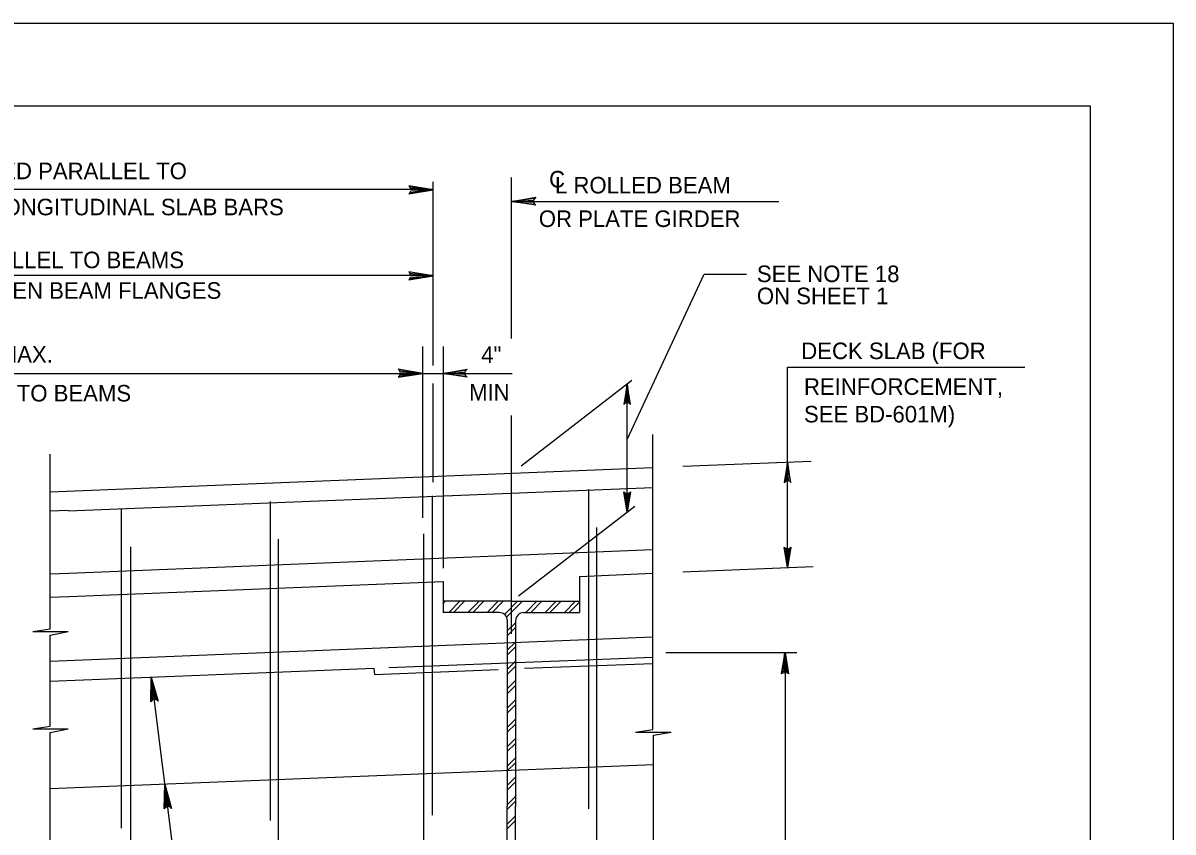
# Model space of a CAD drawing. Extents: x 640009 to 641706, y 298547 to 299735.
# Drawn here: x 641482.9 to 641691.5, y 299588.5 to 299735.2 of the extents above; entities that cross this region are included whole.
import ezdxf

# ---------------------------------------------------------------- set-up
doc = ezdxf.new("R2010")
doc.units = 0
doc.layers.add('1', color=7, linetype='Continuous')
doc.layers.add('PLT-BNDY', color=7, linetype='Continuous')

msp = doc.modelspace()

# ---------------------------------------------------------------- linework, layer by layer
at = {"layer": '1'}
for p, q in [((640890.47, 299720.17), (641676.47, 299720.17)), ((640890.47, 299720.17), (641676.47, 299720.17)), ((641676.47, 299720.17), (641676.47, 299156.17)), ((641676.47, 299720.17), (641676.47, 299156.17)), ((641557.24, 299706.36), (641557.24, 299673.12)), ((641571.49, 299677.96), (641571.49, 299707.14)), ((641411.49, 299705.06), (641557.24, 299705.06)), ((641571.49, 299702.85), (641620.02, 299702.85)), ((641592.47, 299659.66), (641606.46, 299689.66)), ((641606.46, 299689.66), (641614.1, 299689.66)), ((641411.49, 299689.46), (641557.24, 299689.46)), ((641555.37, 299676.52), (641555.37, 299645.47)), ((641559.12, 299676.52), (641559.12, 299636.37)), ((641393.08, 299671.65), (641571.62, 299671.65)), ((641621.59, 299636.45), (641621.59, 299672.77)), ((641621.59, 299672.77), (641664.58, 299672.77)), ((641557.24, 299669.85), (641557.24, 299651.97)), ((641573.24, 299654.91), (641593.36, 299670.41)), ((641592.47, 299646.5), (641592.47, 299669.72)), ((641571.49, 299624.46), (641571.49, 299664.06)), ((641597.12, 299607.1), (641597.12, 299660.6)), ((641487.87, 299625.37), (641487.87, 299657)), ((641487.87, 299650.22), (641597.12, 299654.6)), ((641602.6, 299654.82), (641625.84, 299655.75)), ((641491.12, 299646.72), (641597.12, 299650.97)), ((641585.49, 299650.6), (641585.49, 299592.72)), ((641527.74, 299648.47), (641527.74, 299590.6)), ((641557.12, 299649.47), (641557.12, 299591.6)), ((641487.87, 299646.72), (641491.12, 299646.85)), ((641500.74, 299647.1), (641500.74, 299589.22)), ((641572.79, 299631.35), (641593.87, 299647.58)), ((641586.99, 299518.22), (641586.99, 299643.72)), ((641555.62, 299517.71), (641555.62, 299642.6)), ((641491.24, 299635.47), (641597.12, 299639.72)), ((641502.49, 299515.64), (641502.49, 299640.22)), ((641529.24, 299516.87), (641529.24, 299641.6)), ((641487.87, 299635.34), (641491.24, 299635.47)), ((641583.87, 299634.86), (641597.12, 299635.47)), ((641602.6, 299635.69), (641626.2, 299636.64)), ((641491.24, 299631.22), (641559.12, 299633.94)), ((641559.12, 299633.94), (641559.12, 299628.35)), ((641583.87, 299634.86), (641583.87, 299628.35)), ((641487.87, 299631.09), (641491.24, 299631.22)), ((641571.49, 299630.35), (641559.12, 299630.35)), ((641571.49, 299630.35), (641559.12, 299630.35)), ((641559.12, 299630.35), (641559.12, 299629.35)), ((641571.49, 299630.35), (641559.12, 299630.35)), ((641559.12, 299630.35), (641559.12, 299628.35)), ((641571.49, 299630.35), (641583.87, 299630.35)), ((641571.49, 299630.35), (641583.87, 299630.35)), ((641571.49, 299630.35), (641583.87, 299630.35)), ((641583.87, 299630.35), (641583.87, 299629.35)), ((641583.87, 299630.35), (641583.87, 299628.35)), ((641569.24, 299628.35), (641559.12, 299628.35)), ((641569.24, 299628.35), (641559.12, 299628.35)), ((641573.74, 299628.35), (641583.87, 299628.35)), ((641573.74, 299628.35), (641583.87, 299628.35)), ((641484.74, 299624.87), (641487.87, 299625.37)), ((641570.74, 299626.85), (641570.74, 299593.22)), ((641570.74, 299626.85), (641570.74, 299593.22)), ((641572.24, 299626.85), (641572.24, 299593.22)), ((641572.24, 299626.85), (641572.24, 299593.22)), ((641484.74, 299624.87), (641491.12, 299624.87)), ((641487.87, 299624.22), (641491.12, 299624.87)), ((641487.87, 299615.9), (641487.87, 299624.22)), ((641487.87, 299619.52), (641597.12, 299623.9)), ((641487.99, 299624.87), (641487.99, 299624.87)), ((641599.49, 299621.1), (641623.24, 299621.1)), ((641621.12, 299621.1), (641621.12, 299518.87)), ((641549.24, 299618.35), (641597.12, 299620.22)), ((641573.87, 299618.22), (641597.12, 299619.1)), ((641487.87, 299615.9), (641546.62, 299618.22)), ((641506.19, 299616.62), (641519.99, 299506.6)), ((641546.74, 299617.1), (641546.62, 299618.22)), ((641546.74, 299617.1), (641569.12, 299617.97)), ((641487.87, 299607.73), (641487.87, 299615.9)), ((641484.74, 299607.23), (641487.87, 299607.73)), ((641484.74, 299607.23), (641491.12, 299607.23)), ((641487.87, 299606.58), (641491.12, 299607.23)), ((641487.87, 299581.6), (641487.87, 299606.58)), ((641487.99, 299607.23), (641487.99, 299607.23)), ((641593.99, 299606.6), (641597.12, 299607.1)), ((641593.99, 299606.6), (641600.49, 299606.6)), ((641597.24, 299606.1), (641600.49, 299606.6)), ((641597.24, 299606.6), (641597.24, 299606.6)), ((641597.24, 299530.08), (641597.24, 299606.1)), ((641487.87, 299596.39), (641597.24, 299600.74)), ((641570.74, 299516.21), (641570.74, 299593.22)), ((641570.74, 299516.21), (641570.74, 299593.22)), ((641572.24, 299516.21), (641572.24, 299593.22)), ((641572.24, 299516.21), (641572.24, 299593.22))]:
    msp.add_line(p, q, dxfattribs=at)
for points in [[(641553.08, 299704.42), (641553.25, 299704.73), (641557.32, 299704.95), (641553.08, 299704.42), (641552.87, 299704.23), (641557.32, 299704.95), (641553.25, 299705.15), (641553.09, 299705.46), (641557.32, 299704.95), (641552.87, 299705.68), (641553.09, 299705.46)], [(641575.73, 299702.32), (641575.56, 299702.63), (641571.49, 299702.85), (641575.73, 299702.32), (641575.94, 299702.13), (641571.49, 299702.85), (641575.56, 299703.05), (641575.72, 299703.36), (641571.49, 299702.85), (641575.94, 299703.58), (641575.72, 299703.36)], [(641553.08, 299688.81), (641553.25, 299689.13), (641557.32, 299689.35), (641553.08, 299688.81), (641552.87, 299688.63), (641557.32, 299689.35), (641553.25, 299689.55), (641553.09, 299689.85), (641557.32, 299689.35), (641552.87, 299690.08), (641553.09, 299689.85)], [(641551.2, 299671.14), (641551.38, 299671.45), (641555.44, 299671.67), (641551.2, 299671.14), (641550.99, 299670.95), (641555.44, 299671.67), (641551.38, 299671.87), (641551.22, 299672.18), (641555.44, 299671.67), (641550.99, 299672.4), (641551.22, 299672.18)], [(641563.28, 299671.14), (641563.1, 299671.45), (641559.04, 299671.67), (641563.28, 299671.14), (641563.49, 299670.95), (641559.04, 299671.67), (641563.1, 299671.87), (641563.26, 299672.18), (641559.04, 299671.67), (641563.49, 299672.4), (641563.26, 299672.18)], [(641592.91, 299666.18), (641592.65, 299666.33), (641592.47, 299669.72), (641592.91, 299666.18), (641593.07, 299666.01), (641592.47, 299669.72), (641592.3, 299666.33), (641592.05, 299666.2), (641592.47, 299669.72), (641591.86, 299666.01), (641592.05, 299666.2)], [(641622.03, 299652.04), (641621.77, 299652.19), (641621.59, 299655.58), (641622.03, 299652.04), (641622.19, 299651.87), (641621.59, 299655.58), (641621.42, 299652.19), (641621.17, 299652.06), (641621.59, 299655.58), (641620.98, 299651.87), (641621.17, 299652.06)], [(641592.91, 299650.03), (641592.65, 299649.89), (641592.47, 299646.5), (641592.91, 299650.03), (641593.07, 299650.21), (641592.47, 299646.5), (641592.3, 299649.89), (641592.05, 299650.02), (641592.47, 299646.5), (641591.86, 299650.21), (641592.05, 299650.02)], [(641622.03, 299639.99), (641621.77, 299639.84), (641621.59, 299636.45), (641622.03, 299639.99), (641622.19, 299640.17), (641621.59, 299636.45), (641621.42, 299639.84), (641621.17, 299639.98), (641621.59, 299636.45), (641620.98, 299640.17), (641621.17, 299639.98)], [(641559.12, 299629.97), (641559.49, 299630.35)], [(641560.12, 299628.35), (641562.12, 299630.35)], [(641560.99, 299628.35), (641562.99, 299630.35)], [(641563.62, 299628.35), (641565.62, 299630.35)], [(641564.49, 299628.35), (641566.49, 299630.35)], [(641567.12, 299628.35), (641569.12, 299630.35)], [(641567.99, 299628.35), (641569.99, 299630.35)], [(641570.24, 299627.97), (641572.62, 299630.35)], [(641570.62, 299627.47), (641573.49, 299630.35)], [(641574.12, 299628.35), (641576.12, 299630.35)], [(641574.99, 299628.35), (641576.99, 299630.35)], [(641577.62, 299628.35), (641579.62, 299630.35)], [(641578.49, 299628.35), (641580.49, 299630.35)], [(641581.12, 299628.35), (641583.12, 299630.35)], [(641581.99, 299628.35), (641583.87, 299630.22)], [(641583.74, 299628.35), (641583.87, 299628.47)], [(641570.74, 299624.97), (641572.24, 299626.47)], [(641570.74, 299624.1), (641572.24, 299625.6)], [(641570.74, 299621.47), (641572.24, 299622.97)], [(641570.74, 299620.6), (641572.24, 299622.1)], [(641620.62, 299617.35), (641620.99, 299617.47), (641621.12, 299621.1), (641620.62, 299617.35), (641620.49, 299617.22), (641621.12, 299621.1), (641621.37, 299617.47), (641621.62, 299617.35), (641621.12, 299621.1), (641621.74, 299617.22), (641621.62, 299617.35)], [(641621.55, 299617.52), (641621.29, 299617.67), (641621.1, 299621.06), (641621.55, 299617.52), (641621.71, 299617.35), (641621.1, 299621.06), (641620.94, 299617.67), (641620.68, 299617.54), (641621.1, 299621.06), (641620.5, 299617.35), (641620.68, 299617.54)], [(641570.74, 299617.97), (641572.24, 299619.47)], [(641506.29, 299612.3), (641506.49, 299612.47), (641506.19, 299616.62), (641506.29, 299612.3), (641506.09, 299612.12), (641506.19, 299616.62), (641506.88, 299612.63), (641507.24, 299612.42), (641506.19, 299616.62), (641507.41, 299612.22), (641507.24, 299612.42)], [(641570.74, 299617.1), (641572.24, 299618.6)], [(641570.74, 299614.47), (641572.24, 299615.97)], [(641570.74, 299613.6), (641572.24, 299615.1)], [(641570.74, 299610.97), (641572.24, 299612.47)], [(641570.74, 299610.1), (641572.24, 299611.6)], [(641570.74, 299607.47), (641572.24, 299608.97)], [(641570.74, 299606.6), (641572.24, 299608.1)], [(641570.74, 299603.97), (641572.24, 299605.47)], [(641570.74, 299603.1), (641572.24, 299604.6)], [(641570.74, 299600.47), (641572.24, 299601.97)], [(641570.74, 299599.6), (641572.24, 299601.1)], [(641570.74, 299596.97), (641572.24, 299598.47)], [(641508.72, 299592.89), (641508.92, 299593.06), (641508.62, 299597.22), (641508.72, 299592.89), (641508.53, 299592.71), (641508.62, 299597.22), (641509.31, 299593.23), (641509.67, 299593.02), (641508.62, 299597.22), (641509.85, 299592.82), (641509.67, 299593.02)], [(641570.74, 299596.1), (641572.24, 299597.6)], [(641570.74, 299593.47), (641572.24, 299594.97)], [(641570.74, 299592.6), (641572.24, 299594.1)], [(641570.74, 299589.97), (641572.24, 299591.47)], [(641570.74, 299589.1), (641572.24, 299590.6)]]:
    msp.add_lwpolyline(points, dxfattribs=at)
for centre, start, end in [((641569.29, 299626.83), 0, 90), ((641569.29, 299626.83), 0, 90), ((641573.75, 299626.83), 90, 180), ((641573.75, 299626.83), 90, 180)]:
    msp.add_arc(centre, 1.49, start, end, dxfattribs=at)
at = {"layer": 'PLT-BNDY'}
msp.add_lwpolyline([(640850.47, 299735.17), (641691.47, 299735.17), (641691.47, 299141.17), (640850.47, 299141.17)], close=True, dxfattribs=at)

# ---------------------------------------------------------------- texts
at = {"layer": '1'}
for s, p in [('#4 @ 9" MAX. L-BARS PLACED PARALLEL TO', (641426.44, 299706.86)), ('C', (641578.33, 299705.36)), ('L ROLLED BEAM', (641579.4, 299704.28)), ('AND CENTERED BETWEEN TOP LONGITUDINAL SLAB BARS', (641414.08, 299700.32)), ('OR PLATE GIRDER', (641576.47, 299698.2)), ('#6 @ 9" PLACED PARALLEL TO BEAMS', (641437.29, 299690.73)), ('SEE NOTE 18', (641616.01, 299688.21)), ('AND SPACED BETWEEN BEAM FLANGES', (641439.53, 299685.19)), ('ON SHEET 1', (641616.01, 299684.21)), ('DECK SLAB (FOR', (641624.06, 299674.25)), ('#4 TIES @ 9" MAX.', (641452.97, 299673.61)), ('4"', (641566.02, 299673.54)), ('REINFORCEMENT,', (641624.55, 299667.77)), ('PLACED PARALLEL TO BEAMS', (641443.23, 299666.57)), ('MIN', (641563.82, 299666.74)), ('SEE BD-601M)', (641624.55, 299662.77))]:
    msp.add_text(s, height=3, dxfattribs=at).set_placement(p)

doc.saveas('drawing.dxf')
